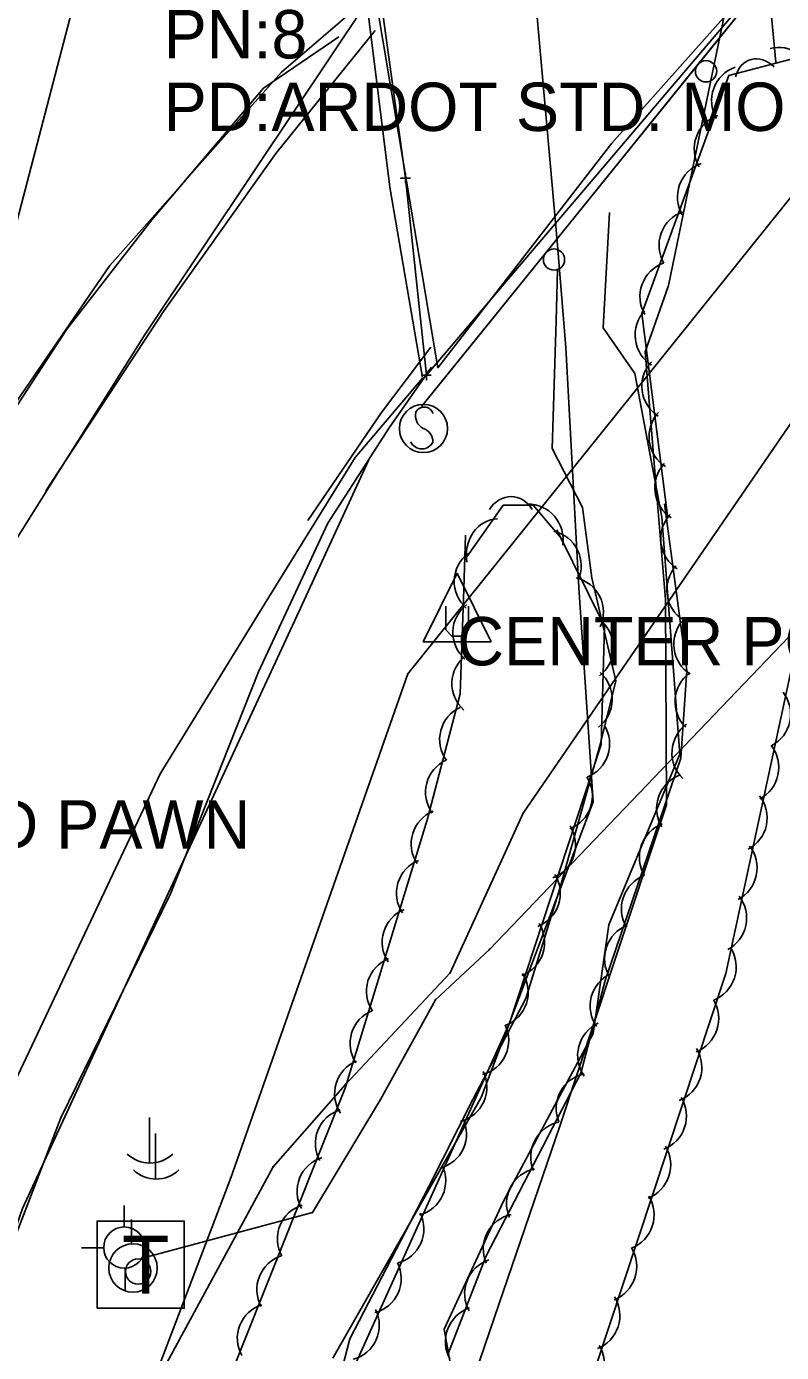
# Model space of a CAD drawing. Extents: x 978516 to 993312, y 1836504 to 1846212.
# Drawn here: x 992686.2 to 992764.3, y 1840378.8 to 1840515.9 of the extents above; entities that cross this region are included whole.
import ezdxf

# ---------------------------------------------------------------- set-up
doc = ezdxf.new("R2010")
doc.units = 0
for name, color, linetype in [('S_BASELINE', 7, 'Continuous'), ('S_BRIDGE', 7, 'Continuous'), ('S_EDGE_PAVEMENT', 7, 'Continuous'), ('S_FIBER_OPTIC_CABLE', 7, 'Continuous'), ('S_GAS_UTILITIES', 7, 'Continuous'), ('S_GUARDRAIL', 7, 'Continuous'), ('S_HEADWALL', 7, 'Continuous'), ('S_PRIMARY_CTL_ANNOT', 7, 'Continuous'), ('S_SHOULDER', 7, 'Continuous'), ('S_SIGN', 7, 'Continuous'), ('S_SIGN_ANNOT', 7, 'Continuous'), ('S_STR_PT_SYM', 7, 'Continuous'), ('S_STREAM', 7, 'Continuous'), ('S_TELEPHONE_UTILITIES', 7, 'Continuous'), ('S_TREE', 7, 'Continuous'), ('S_UNDERGROUND_CABLE', 7, 'Continuous'), ('S_UTILITY_POLE', 7, 'Continuous'), ('S_UTILITY_POLE_ANNOT', 7, 'Continuous'), ('S_UTL_PT_SYM', 7, 'Continuous')]:
    doc.layers.add(name, color=color, linetype=linetype)

msp = doc.modelspace()

# ---------------------------------------------------------------- linework, layer by layer
at = {"layer": 'S_BASELINE'}
msp.add_line((992692.91, 1840525.06), (992469.46, 1839669.75), dxfattribs=at)
at = {"layer": 'S_BRIDGE'}
for p, q in [((992727.57, 1840479.81), (992763.66, 1840522.31)), ((992722.66, 1840520.07), (992725.42, 1840500.17)), ((992725.42, 1840500.17), (992727.57, 1840479.81))]:
    msp.add_line(p, q, dxfattribs=at)
msp.add_lwpolyline([(992741.67, 1840541.48), (992762.9, 1840562.2), (992763.6, 1840522.8), (992746.71, 1840503.81), (992728.74, 1840480.59), (992722.25, 1840519.42)], close=True, dxfattribs=at)
at = {"layer": 'S_EDGE_PAVEMENT'}
for points in [[(992727.17, 1840479.58), (992723.79, 1840499.26), (992721.4, 1840518.33), (992709.95, 1840501.18), (992698.5, 1840484.04), (992688.92, 1840468.82), (992679.35, 1840453.6), (992673.45, 1840441.41), (992667.56, 1840429.21), (992661.66, 1840417.01)], [(992688.26, 1840467.86), (992700.48, 1840486.5), (992712, 1840502.74), (992722.26, 1840515.46)], [(992715.31, 1840464.78), (992722.92, 1840475.97), (992728.04, 1840482.7)], [(992727.17, 1840479.52), (992720.19, 1840471.32), (992710.13, 1840454.97), (992700.07, 1840438.61), (992689.95, 1840417.21), (992679.83, 1840395.82), (992671.68, 1840374.91)]]:
    msp.add_lwpolyline(points, dxfattribs=at)
at = {"layer": 'S_FIBER_OPTIC_CABLE'}
for p, q in [((992737.56, 1840434.53), (992781.05, 1840497.97)), ((992734.08, 1840420.45), (992767.58, 1840455.45)), ((992730.03, 1840418.03), (992737.56, 1840434.53)), ((992728.5, 1840415.25), (992734.08, 1840420.45)), ((992719.2, 1840406.49), (992730.03, 1840418.03)), ((992722.82, 1840404.92), (992728.5, 1840415.25)), ((992711.73, 1840397.96), (992719.2, 1840406.49)), ((992715.78, 1840393.27), (992722.82, 1840404.92)), ((992696.75, 1840370.36), (992711.73, 1840397.96)), ((992698.75, 1840388.67), (992715.78, 1840393.27))]:
    msp.add_line(p, q, dxfattribs=at)
at = {"layer": 'S_GAS_UTILITIES'}
for p, q in [((992725.65, 1840448.94), (992770.68, 1840505.03)), ((992707.36, 1840396.84), (992725.65, 1840448.94)), ((992689.06, 1840348.91), (992707.36, 1840396.84))]:
    msp.add_line(p, q, dxfattribs=at)
at = {"layer": 'S_GUARDRAIL'}
for points in [[(992763.45, 1840521.65), (992727.06, 1840476.56)], [(992763.45, 1840521.65), (992755.6, 1840511.92)], [(992755.6, 1840511.92), (992739.9, 1840492.46)], [(992739.9, 1840492.46), (992732.04, 1840482.74)], [(992732.04, 1840482.74), (992727.06, 1840476.56)]]:
    msp.add_lwpolyline(points, dxfattribs=at)
for centre in [(992756.46, 1840511.23), (992740.75, 1840491.77)]:
    msp.add_circle(centre, 1.1, dxfattribs=at)
at = {"layer": 'S_HEADWALL'}
msp.add_lwpolyline([(992763, 1840519.48), (992763.68, 1840512.17)], dxfattribs=at)
at = {"layer": 'S_SHOULDER'}
for points in [[(992679.93, 1840469.45), (992694.86, 1840491.14), (992712.59, 1840511.13), (992721.74, 1840519.04)], [(992718.52, 1840514.78), (992710.74, 1840509.48), (992699.21, 1840495.89), (992690.4, 1840484.57), (992681.65, 1840471.21), (992672.91, 1840457.84), (992672.34, 1840456.65)], [(992717.38, 1840464.52), (992723.71, 1840474.36), (992728.11, 1840480.64)], [(992721.59, 1840470.99), (992713.92, 1840454.4), (992706.25, 1840437.82), (992696.04, 1840415.74), (992685.83, 1840393.66), (992678.72, 1840373.27)], [(992717.38, 1840464.52), (992710.22, 1840449.16), (992701.13, 1840426.2), (992689.81, 1840403.05), (992677.84, 1840371.95), (992667.61, 1840339.8), (992652.64, 1840298.18), (992643.63, 1840265.47), (992625.17, 1840202.99), (992614.29, 1840160.82), (992602.66, 1840116.12)]]:
    msp.add_lwpolyline(points, dxfattribs=at)
at = {"layer": 'S_SIGN'}
msp.add_circle((992727.26, 1840474.3), 2.49, dxfattribs=at)
for centre, radius, start, end in [((992727.94, 1840475.62), 1.5, 167.1196, 241.9813), ((992727.33, 1840475.57), 0.95, 16.5258, 156.8957), ((992726.84, 1840472.96), 1.4, 358.6529, 73.7063), ((992727.1, 1840473.47), 1.28, 204.641, 335.359)]:
    msp.add_arc(centre, radius, start, end, dxfattribs=at)
at = {"layer": 'S_STR_PT_SYM'}
for points in [[(992725.42, 1840500.17), (992725.42, 1840500.67), (992725.42, 1840500.17), (992724.92, 1840500.17), (992725.42, 1840500.17), (992725.42, 1840499.67), (992725.42, 1840500.17), (992725.92, 1840500.17)], [(992727.57, 1840479.81), (992727.57, 1840480.31), (992727.57, 1840479.81), (992727.07, 1840479.81), (992727.57, 1840479.81), (992727.57, 1840479.31), (992727.57, 1840479.81), (992728.07, 1840479.81)]]:
    msp.add_lwpolyline(points, dxfattribs=at)
at = {"layer": 'S_STREAM'}
for points in [[(992758.28, 1840595.17), (992757.44, 1840589.73), (992757.19, 1840573.18), (992756.93, 1840556.62), (992757.65, 1840536.86), (992758.37, 1840517.1), (992755.48, 1840503.1), (992752.59, 1840489.1), (992750.17, 1840482.23), (992751.22, 1840469.43), (992752.27, 1840456.64), (992752.39, 1840435.4), (992746.88, 1840418.83), (992741.38, 1840402.27), (992735.04, 1840383.73), (992728.7, 1840365.18)], [(992738.56, 1840569.62), (992736.23, 1840559.11), (992737.44, 1840539.91), (992738.66, 1840520.72), (992739.87, 1840507.19), (992741.09, 1840493.67), (992741.97, 1840482.66), (992743.33, 1840457.87), (992744.81, 1840435.72), (992739.02, 1840420.42), (992733.23, 1840405.13), (992725.57, 1840391.67), (992717.91, 1840378.21)], [(992751.9, 1840465.14), (992749.1, 1840480), (992745.82, 1840484.7), (992746.48, 1840496.62)], [(992743.7, 1840466.14), (992740.56, 1840472.23), (992740.96, 1840485.42), (992741.11, 1840490.71)], [(992715.14, 1840362.74), (992719.66, 1840380.19), (992727.78, 1840395.89), (992732.36, 1840404.92), (992737.84, 1840415.38), (992741.36, 1840426.74), (992745.53, 1840441.65), (992747.14, 1840448.22), (992744.67, 1840458.87), (992743.7, 1840466.14)], [(992751.9, 1840465.14), (992753.76, 1840440.65), (992746.42, 1840422.99), (992744.79, 1840411.76), (992735.52, 1840394.42), (992729.41, 1840381.19), (992730.5, 1840375.02), (992722.65, 1840349.89), (992713.89, 1840327.1), (992701.8, 1840298.75), (992680.46, 1840249.31), (992675.27, 1840237.31), (992676.06, 1840233.45), (992673.73, 1840221.5), (992666.9, 1840214.58), (992664.48, 1840209.97), (992661.8, 1840193.68), (992657.68, 1840165.91), (992654.52, 1840140.98), (992654.44, 1840125.57), (992654.52, 1840111.92)]]:
    msp.add_lwpolyline(points, dxfattribs=at)
at = {"layer": 'S_TELEPHONE_UTILITIES'}
msp.add_lwpolyline([(992693.54, 1840383.36), (992693.54, 1840392.36), (992702.54, 1840392.36), (992702.54, 1840383.36)], close=True, dxfattribs=at)
at = {"layer": 'S_TREE'}
for points in [[(992752.51, 1840465.02), (992749.82, 1840486.19), (992758.82, 1840510.8), (992765.12, 1840512.46), (992768.71, 1840509.72), (992772.63, 1840501.19)], [(992768.84, 1840467.93), (992765.62, 1840451.06), (992758.49, 1840417.97), (992731.36, 1840335.88)], [(992729.78, 1840378.57), (992733.73, 1840388.79), (992743.51, 1840407.67), (992746.05, 1840417.24), (992753.85, 1840440.22), (992754.47, 1840449.28), (992752.16, 1840466.52)], [(992731.5, 1840460.69), (992735.5, 1840466.36), (992738.59, 1840466.36), (992741.7, 1840462.71)], [(992741.05, 1840463.84), (992745.98, 1840453.87), (992745.62, 1840441.63), (992736.16, 1840412.83), (992717.26, 1840370.96), (992704.39, 1840328.82), (992691.36, 1840292.3), (992674.25, 1840260.52), (992668.39, 1840240.56), (992660.65, 1840227.05), (992655.21, 1840228.91), (992669.09, 1840269.72), (992682.27, 1840299.38), (992691.67, 1840331.36), (992703.25, 1840366.22), (992719.16, 1840406.11), (992727.68, 1840433.94), (992731.06, 1840446.88), (992731.43, 1840457.73), (992731.62, 1840463.28)]]:
    msp.add_lwpolyline(points, dxfattribs=at)
for centre, major_axis, ratio, start_param, end_param in [((992763.95, 1840510.07), (0.25, 3.63), 0.946906, 4.8381, 6.611301), ((992762.18, 1840508.97), (1.23, -3.43), 0.732195, 2.191587, 3.964788), ((992760.65, 1840508.21), (-0.73, -3.57), 0.992465, 3.676166, 5.449366), ((992758.86, 1840503.22), (-0.73, -3.57), 0.992465, 3.676166, 5.449366), ((992757.12, 1840498.24), (-0.73, -3.57), 0.992465, 3.676166, 5.449366), ((992755.22, 1840493.25), (-0.73, -3.57), 0.992465, 3.676166, 5.449366), ((992753.25, 1840487.96), (-0.73, -3.57), 0.992465, 3.676166, 5.449366), ((992752.72, 1840483.94), (0.58, -3.6), 0.98483, 3.792909, 5.566109), ((992753.42, 1840478.68), (0.58, -3.6), 0.98483, 3.792909, 5.566109), ((992754.16, 1840473.45), (0.58, -3.6), 0.98483, 3.792909, 5.566109), ((992754.76, 1840468.15), (0.58, -3.6), 0.98483, 3.792909, 5.566109), ((992736.23, 1840463.63), (-0.24, -3.64), 0.78233, 2.305913, 4.079113), ((992738.25, 1840462.86), (-1.08, 3.48), 0.942127, 4.252192, 6.025393), ((992734.97, 1840461.33), (-0.33, -3.63), 0.901276, 3.257436, 5.030637), ((992755.36, 1840462.9), (0.48, -3.61), 0.984341, 3.825789, 5.598989), ((992739.92, 1840460.13), (-1.61, 3.27), 0.999887, 3.825789, 5.598989), ((992734.08, 1840458.49), (-0.12, -3.64), 0.999844, 3.825789, 5.598989), ((992755.99, 1840457.61), (0.48, -3.61), 0.984341, 3.825789, 5.598989), ((992742.22, 1840455.31), (-1.61, 3.27), 0.999887, 3.825789, 5.598989), ((992733.94, 1840453.21), (-3.56, -0.77), 0.997372, 5.150313, 6.923513), ((992743.25, 1840451.63), (0.11, 3.64), 0.999844, 3.825789, 5.598989), ((992756.71, 1840452), (0.48, -3.61), 0.984341, 3.825789, 5.598989), ((992733.84, 1840447.94), (-3.56, -0.77), 0.997372, 5.150313, 6.923513), ((992743.13, 1840446.32), (0.11, 3.64), 0.999844, 3.825789, 5.598989), ((992756.83, 1840446.07), (-0.25, -3.63), 0.98229, 3.825789, 5.598989), ((992761.62, 1840444.74), (1, 3.5), 0.981544, 3.893975, 5.667176), ((992732.58, 1840442.16), (-2.45, -2.7), 0.999806, 4.306312, 6.079513), ((992742.86, 1840441.67), (1.14, 3.46), 0.999851, 3.825789, 5.598989), ((992756.51, 1840440.78), (-0.25, -3.63), 0.98229, 3.825789, 5.598989), ((992760.4, 1840439.23), (1, 3.5), 0.981544, 3.893975, 5.667176), ((992731.12, 1840436.7), (-2.45, -2.7), 0.999806, 4.306312, 6.079513), ((992754.93, 1840435.05), (-1.22, -3.43), 0.981619, 3.839398, 5.612598), ((992741.07, 1840436.31), (1.14, 3.46), 0.999851, 3.825789, 5.598989), ((992759.2, 1840434.03), (1, 3.5), 0.981544, 3.893975, 5.667176), ((992729.63, 1840431.36), (1.83, -3.15), 0.999674, 3.000895, 4.774096), ((992739.34, 1840431.27), (1.14, 3.46), 0.999851, 3.825789, 5.598989), ((992753.15, 1840430.03), (-1.22, -3.43), 0.981619, 3.839398, 5.612598), ((992758.16, 1840428.85), (1, 3.5), 0.981544, 3.893975, 5.667176), ((992728.11, 1840426.27), (1.83, -3.15), 0.999674, 3.000895, 4.774096), ((992737.76, 1840426.23), (1.14, 3.46), 0.999851, 3.825789, 5.598989), ((992751.3, 1840424.69), (-1.22, -3.43), 0.981619, 3.839398, 5.612598), ((992757.08, 1840423.66), (1, 3.5), 0.981544, 3.893975, 5.667176), ((992726.64, 1840421.2), (1.83, -3.15), 0.999674, 3.000895, 4.774096), ((992736.14, 1840421.17), (1.14, 3.46), 0.999851, 3.825789, 5.598989), ((992749.55, 1840419.54), (-1.22, -3.43), 0.981619, 3.839398, 5.612598), ((992755.99, 1840418.61), (1.32, 3.4), 0.981556, 3.876903, 5.650104), ((992725.01, 1840416.12), (1.83, -3.15), 0.999674, 3.000895, 4.774096), ((992734.44, 1840416.01), (1.14, 3.46), 0.999851, 3.825789, 5.598989), ((992748.06, 1840414.63), (-0.93, -3.52), 0.981567, 3.825789, 5.598989), ((992754.18, 1840413.26), (1.32, 3.4), 0.981556, 3.876903, 5.650104), ((992723.32, 1840410.73), (1.83, -3.15), 0.999674, 3.000895, 4.774096), ((992732.43, 1840411.04), (-1.74, 3.2), 0.999615, 2.902934, 4.676134), ((992746.77, 1840409.51), (-0.93, -3.52), 0.981567, 3.825789, 5.598989), ((992752.44, 1840408.22), (1.32, 3.4), 0.981556, 3.876903, 5.650104), ((992721.72, 1840405.53), (1.83, -3.15), 0.999674, 3.000895, 4.774096), ((992730.17, 1840406.21), (-1.74, 3.2), 0.999615, 2.902934, 4.676134), ((992744.58, 1840404.05), (-1.68, -3.24), 0.982327, 3.825789, 5.598989), ((992750.85, 1840403.18), (1.32, 3.4), 0.981556, 3.876903, 5.650104), ((992719.74, 1840400.39), (2.17, -2.93), 0.999478, 2.808598, 4.581798), ((992728.07, 1840401.36), (-1.74, 3.2), 0.999615, 2.902934, 4.676134), ((992741.95, 1840399.05), (-1.68, -3.24), 0.982327, 3.825789, 5.598989), ((992749.22, 1840398.13), (1.32, 3.4), 0.981556, 3.876903, 5.650104), ((992717.85, 1840395.45), (2.17, -2.93), 0.999478, 2.808598, 4.581798), ((992725.92, 1840396.52), (-1.74, 3.2), 0.999615, 2.902934, 4.676134), ((992739.45, 1840394.22), (-1.68, -3.24), 0.982327, 3.825789, 5.598989), ((992747.51, 1840392.97), (1.32, 3.4), 0.981556, 3.876903, 5.650104), ((992715.81, 1840390.53), (2.17, -2.93), 0.999478, 2.808598, 4.581798), ((992723.67, 1840391.56), (-1.74, 3.2), 0.999615, 2.902934, 4.676134), ((992737.04, 1840389.5), (-1.68, -3.24), 0.982327, 3.825789, 5.598989), ((992745.71, 1840387.62), (1.32, 3.4), 0.981556, 3.876903, 5.650104), ((992713.69, 1840385.3), (2.17, -2.93), 0.999478, 2.808598, 4.581798), ((992721.32, 1840386.43), (-1.74, 3.2), 0.999615, 2.902934, 4.676134), ((992735.1, 1840384.9), (-1.31, -3.4), 0.981738, 3.825789, 5.598989), ((992711.67, 1840380.24), (2.17, -2.93), 0.999478, 2.808598, 4.581798), ((992743.97, 1840382.57), (1.32, 3.4), 0.981556, 3.876903, 5.650104), ((992719.06, 1840381.6), (-1.74, 3.2), 0.999615, 2.902934, 4.676134), ((992733.11, 1840379.95), (-1.31, -3.4), 0.981738, 3.825789, 5.598989), ((992742.38, 1840377.54), (1.32, 3.4), 0.981556, 3.876903, 5.650104)]:
    msp.add_ellipse(centre, major_axis=major_axis, ratio=ratio, start_param=start_param, end_param=end_param, dxfattribs=at)
at = {"layer": 'S_UNDERGROUND_CABLE'}
for p, q in [((992730.76, 1840459.34), (992727.23, 1840452.25)), ((992730.76, 1840459.34), (992734.25, 1840452.25)), ((992729.56, 1840453.49), (992729.56, 1840455.93)), ((992731.92, 1840455.93), (992731.92, 1840453.49)), ((992730.18, 1840452.83), (992729.56, 1840453.49)), ((992731.92, 1840453.49), (992731.38, 1840452.83)), ((992727.23, 1840452.25), (992734.25, 1840452.25)), ((992731.38, 1840452.83), (992730.18, 1840452.83))]:
    msp.add_line(p, q, dxfattribs=at)
at = {"layer": 'S_UTILITY_POLE'}
for p, q in [((992698.94, 1840403.07), (992698.94, 1840398.34)), ((992699.58, 1840401.42), (992699.58, 1840396.69)), ((992696.35, 1840391.74), (992696.35, 1840393.99)), ((992697.11, 1840390.04), (992697.11, 1840392.52)), ((992694.26, 1840389.61), (992691.93, 1840389.61)), ((992696.43, 1840385.19), (992696.43, 1840387.52))]:
    msp.add_line(p, q, dxfattribs=at)
for centre, radius in [((992696.35, 1840389.63), 2.13), ((992697.25, 1840387.52), 2.5), ((992697.78, 1840387.15), 1.31)]:
    msp.add_circle(centre, radius, dxfattribs=at)
for centre in [(992699.01, 1840401.77), (992699.65, 1840400.12)]:
    msp.add_arc(centre, 3.41, 226.3972, 313.6028, dxfattribs=at)
at = {"layer": 'S_UTL_PT_SYM'}
for points in [[(992725.65, 1840448.94), (992725.65, 1840448.99), (992725.65, 1840448.94), (992725.6, 1840448.94), (992725.65, 1840448.94), (992725.65, 1840448.89), (992725.65, 1840448.94), (992725.7, 1840448.94)], [(992737.56, 1840434.53), (992737.56, 1840434.58), (992737.56, 1840434.53), (992737.51, 1840434.53), (992737.56, 1840434.53), (992737.56, 1840434.48), (992737.56, 1840434.53), (992737.61, 1840434.53)], [(992734.08, 1840420.45), (992734.08, 1840420.5), (992734.08, 1840420.45), (992734.03, 1840420.45), (992734.08, 1840420.45), (992734.08, 1840420.4), (992734.08, 1840420.45), (992734.13, 1840420.45)], [(992730.03, 1840418.03), (992730.03, 1840418.08), (992730.03, 1840418.03), (992729.98, 1840418.03), (992730.03, 1840418.03), (992730.03, 1840417.98), (992730.03, 1840418.03), (992730.08, 1840418.03)], [(992728.5, 1840415.25), (992728.5, 1840415.3), (992728.5, 1840415.25), (992728.45, 1840415.25), (992728.5, 1840415.25), (992728.5, 1840415.2), (992728.5, 1840415.25), (992728.55, 1840415.25)], [(992719.2, 1840406.49), (992719.2, 1840406.54), (992719.2, 1840406.49), (992719.15, 1840406.49), (992719.2, 1840406.49), (992719.2, 1840406.44), (992719.2, 1840406.49), (992719.25, 1840406.49)], [(992722.82, 1840404.92), (992722.82, 1840404.97), (992722.82, 1840404.92), (992722.77, 1840404.92), (992722.82, 1840404.92), (992722.82, 1840404.87), (992722.82, 1840404.92), (992722.87, 1840404.92)], [(992711.73, 1840397.96), (992711.73, 1840398.01), (992711.73, 1840397.96), (992711.68, 1840397.96), (992711.73, 1840397.96), (992711.73, 1840397.91), (992711.73, 1840397.96), (992711.78, 1840397.96)], [(992707.36, 1840396.84), (992707.36, 1840396.89), (992707.36, 1840396.84), (992707.31, 1840396.84), (992707.36, 1840396.84), (992707.36, 1840396.79), (992707.36, 1840396.84), (992707.41, 1840396.84)], [(992715.78, 1840393.27), (992715.78, 1840393.32), (992715.78, 1840393.27), (992715.73, 1840393.27), (992715.78, 1840393.27), (992715.78, 1840393.22), (992715.78, 1840393.27), (992715.83, 1840393.27)], [(992698.75, 1840388.67), (992698.75, 1840388.72), (992698.75, 1840388.67), (992698.7, 1840388.67), (992698.75, 1840388.67), (992698.75, 1840388.62), (992698.75, 1840388.67), (992698.8, 1840388.67)]]:
    msp.add_lwpolyline(points, dxfattribs=at)

# ---------------------------------------------------------------- texts
at = {"layer": 'S_PRIMARY_CTL_ANNOT'}
for s, p in [('PN:8', (992700.41, 1840512.56)), ('PD:ARDOT STD. MON. STAMPED PN:8', (992700.41, 1840505.06))]:
    msp.add_text(s, height=5, dxfattribs=at).set_placement(p)
at = {"layer": 'S_SIGN_ANNOT'}
msp.add_text('.40 TO PST MTL WD PAWN', height=5, dxfattribs=at).set_placement((992623.93, 1840430.88))
at = {"layer": 'S_TELEPHONE_UTILITIES'}
msp.add_text('T', height=6, dxfattribs=at).set_placement((992696.1, 1840384.86))
at = {"layer": 'S_UTILITY_POLE_ANNOT'}
msp.add_text('CENTER POINT', height=5, dxfattribs=at).set_placement((992730.76, 1840449.81))

doc.saveas('drawing.dxf')
